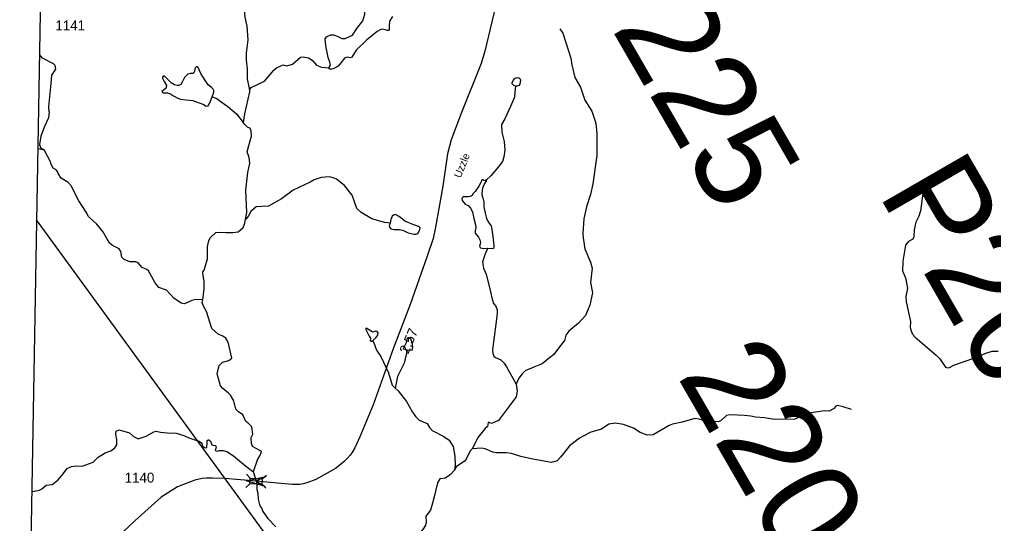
# Model space of a CAD drawing. Extents: x 2056842 to 2160602, y 826753 to 1016856.
# Drawn here: x 2058297 to 2070531, y 912171 to 918502 of the extents above; entities that cross this region are included whole.
import ezdxf

# ---------------------------------------------------------------- set-up
doc = ezdxf.new("R2010")
doc.units = 0
for name, color, linetype in [('Exist Boundary Political CountyLine', 7, 'Continuous'), ('Exist Hydrographic Creek Single Shore', 7, 'Continuous'), ('Exist Hydrographic Misc Water Feature', 7, 'Continuous'), ('Exist Road Secondary Mileage Hundredths English Label', 7, 'Continuous'), ('Exist Road Secondary Structure Pipe Number Label', 7, 'Continuous'), ('Exist Road Secondary Structure Standard Bridge Attributed CELL', 7, 'Continuous'), ('Exist Road Secondary Structure Standard Bridge CELL', 7, 'Continuous'), ('Exist Road Secondary Structure Standard Bridge Number Label', 7, 'Continuous'), ('Exist Road Secondary Type 41 Attributed', 7, 'Continuous'), ('Exist Road Secondary Type 51 Label', 7, 'Continuous'), ('Exist Road Secondary Type 51 Number Label', 7, 'Continuous'), ('Exist Utilities Electrical Transmission Line', 7, 'Continuous')]:
    doc.layers.add(name, color=color, linetype=linetype)

msp = doc.modelspace()

# ---------------------------------------------------------------- linework, layer by layer
at = {"layer": 'Exist Boundary Political CountyLine'}
msp.add_lwpolyline([(2059857, 1016190), (2059992, 1014583), (2060288, 1010619), (2060242, 1008371), (2060207, 1006771), (2060178, 1005306), (2060151, 1003994), (2060127, 1003052), (2060086, 1001470), (2060083, 1001043), (2059970, 996247), (2059900, 992965), (2059781, 986401), (2059707, 983126), (2059583, 976558), (2059387, 966720), (2059310, 963431), (2059198, 956451), (2059161, 955539), (2058927, 940380), (2058725, 928102), (2058408, 910016), (2058297, 904796)], dxfattribs=at)
at = {"layer": 'Exist Hydrographic Creek Single Shore'}
for points in [[(2060896, 919776), (2060908, 919728), (2060960, 919628), (2061040, 919384), (2061087, 919029), (2061128, 918532), (2061154, 918420), (2061166, 918247), (2061145, 918081), (2061145, 917989), (2061157, 917881), (2061157, 917757), (2061186, 917613)], [(2062182, 917893), (2062204, 917929), (2062196, 917967), (2062173, 918024), (2062145, 918170), (2062137, 918259), (2062153, 918282), (2062206, 918308), (2062247, 918311), (2062288, 918293), (2062347, 918262), (2062386, 918264), (2062480, 918303), (2062534, 918390), (2062611, 918485), (2062636, 918567), (2062636, 918592), (2062644, 918618)], [(2062984, 918541), (2062946, 918479), (2062941, 918418), (2062941, 918367), (2062933, 918362), (2062918, 918362), (2062859, 918382), (2062836, 918377), (2062790, 918349), (2062654, 918244), (2062524, 918116), (2062470, 918029), (2062450, 918021), (2062416, 918029), (2062380, 918016), (2062339, 917962), (2062299, 917914), (2062247, 917886), (2062204, 917873), (2062191, 917883), (2062182, 917893)], [(2065082, 918386), (2065120, 918330), (2065220, 918018), (2065233, 917934), (2065273, 917773), (2065343, 917653), (2065399, 917489), (2065484, 917349), (2065534, 917201), (2065550, 917065), (2065549, 916793), (2065500, 916437), (2065470, 916305), (2065418, 916149), (2065386, 915997), (2065371, 915813), (2065376, 915761), (2065397, 915621), (2065467, 915453), (2065489, 915377), (2065470, 915197), (2065494, 915069), (2065461, 914913), (2065405, 914785), (2065319, 914689), (2065195, 914588), (2065161, 914536), (2065141, 914468), (2065080, 914390), (2065010, 914292), (2064954, 914250), (2064863, 914177), (2064758, 914136), (2064650, 914087), (2064611, 914053), (2064570, 913997), (2064535, 913923)], [(2058668, 917344), (2058664, 917404), (2058695, 917696), (2058705, 917804), (2058753, 917876), (2058745, 917924), (2058725, 917944), (2058585, 918018), (2058547, 918062)], [(2061185, 917613), (2061209, 917649), (2061373, 917729), (2061493, 917867), (2061525, 917895), (2061609, 917931), (2061657, 917919), (2061725, 917940), (2061825, 918028), (2061860, 918032), (2061928, 918022), (2061973, 917990), (2062027, 917930), (2062092, 917903), (2062182, 917893)], [(2061186, 917613), (2061185, 917593), (2061123, 917318), (2061106, 917209)], [(2058668, 917344), (2058662, 917268), (2058610, 917156), (2058566, 917036), (2058547, 916930), (2058563, 916892), (2058595, 916868)], [(2061138, 915993), (2061152, 916077), (2061140, 916357), (2061167, 916580), (2061191, 916697), (2061183, 916768), (2061155, 916841), (2061178, 916920), (2061210, 917037), (2061208, 917109), (2061192, 917136), (2061160, 917149), (2061126, 917182), (2061106, 917208)], [(2060599, 914981), (2060513, 914985), (2060460, 914973), (2060368, 914929), (2060328, 914939), (2060236, 915003), (2060142, 915103), (2060046, 915135), (2060002, 915194), (2059918, 915346), (2059898, 915362), (2059837, 915386), (2059786, 915446), (2059758, 915458), (2059685, 915458), (2059610, 915488), (2059581, 915516), (2059569, 915588), (2059549, 915620), (2059465, 915663), (2059429, 915691), (2059345, 915841), (2059269, 915933), (2059184, 916005), (2059164, 916029), (2059136, 916081), (2059042, 916224), (2058946, 916412), (2058910, 916456), (2058820, 916508), (2058783, 916568), (2058775, 916592), (2058759, 916612), (2058719, 916636), (2058695, 916680), (2058683, 916724), (2058611, 916856), (2058595, 916868)], [(2060599, 914981), (2060609, 915049), (2060618, 915117), (2060618, 915214), (2060598, 915313), (2060602, 915334), (2060618, 915354), (2060657, 915494), (2060657, 915646), (2060677, 915726), (2060697, 915762), (2060765, 915826), (2060821, 915830), (2060890, 915826), (2060977, 915828), (2061043, 915836), (2061105, 915888), (2061126, 915945), (2061138, 915993)], [(2061236, 912813), (2061242, 912836), (2061288, 912972), (2061318, 913021), (2061337, 913072), (2061316, 913089), (2061222, 913139), (2061210, 913175), (2061209, 913251), (2061229, 913295), (2061215, 913387), (2061167, 913437), (2061139, 913451), (2061103, 913535), (2061047, 913574), (2061014, 913608), (2060991, 913714), (2060946, 913782), (2060922, 913810), (2060850, 913866), (2060820, 913902), (2060780, 914051), (2060804, 914157), (2060848, 914198), (2060927, 914218), (2060965, 914248), (2060919, 914450), (2060887, 914498), (2060853, 914526), (2060791, 914550), (2060711, 914622), (2060645, 914833), (2060610, 914902), (2060592, 914949), (2060599, 914981)], [(2070343, 914268), (2070433, 914312), (2070513, 914336), (2070589, 914337)], [(2064535, 913923), (2064547, 913832), (2064535, 913763), (2064438, 913634), (2064312, 913465), (2064225, 913428), (2064197, 913441), (2064183, 913439), (2064175, 913388), (2064141, 913361), (2064059, 913256), (2063984, 913108)], [(2059493, 913122), (2059519, 913158), (2059522, 913228), (2059506, 913295), (2059510, 913332), (2059549, 913348), (2059677, 913308), (2059729, 913262), (2059789, 913234), (2059887, 913268), (2059986, 913324), (2060012, 913330), (2060067, 913320), (2060150, 913309), (2060264, 913304), (2060363, 913276), (2060425, 913249), (2060489, 913226), (2060554, 913205), (2060581, 913188), (2060589, 913175), (2060590, 913150), (2060620, 913127), (2060639, 913122), (2060649, 913132), (2060655, 913184), (2060656, 913214), (2060665, 913222), (2060677, 913220), (2060695, 913207), (2060713, 913161), (2060728, 913154), (2060756, 913150), (2060768, 913139), (2060765, 913115), (2060755, 913093), (2060768, 913082), (2060783, 913081), (2060807, 913088), (2060855, 913088), (2060901, 913075), (2060985, 913021), (2061138, 912895), (2061224, 912829), (2061237, 912813)], [(2058453, 912573), (2058482, 912576), (2058547, 912591), (2058580, 912605), (2058633, 912651), (2058706, 912662), (2058781, 912716), (2058829, 912772), (2058896, 912861), (2058949, 912889), (2059004, 912897), (2059084, 912893), (2059222, 912940), (2059287, 913005), (2059373, 913060), (2059446, 913084), (2059493, 913122)], [(2063984, 913108), (2063958, 913084), (2063908, 912980), (2063884, 912948), (2063788, 912888), (2063760, 912842)], [(2061237, 912813), (2061270, 912701), (2061279, 912659), (2061277, 912599), (2061289, 912553), (2061297, 912475), (2061315, 912395), (2061341, 912359), (2061354, 912323), (2061418, 912235), (2061518, 912131)], [(2063760, 912842), (2063712, 912785), (2063646, 912742), (2063578, 912732), (2063547, 912682), (2063505, 912505), (2063486, 912427), (2063461, 912340), (2063401, 912264), (2063404, 912187), (2063398, 912152), (2063373, 912108), (2063304, 912025), (2063196, 911937), (2063074, 911780), (2063058, 911741), (2063042, 911649), (2063041, 911592), (2063067, 911536), (2063191, 911369), (2063228, 911293), (2063299, 911113), (2063310, 911045), (2063302, 910980)]]:
    msp.add_lwpolyline(points, dxfattribs=at)
at = {"layer": 'Exist Hydrographic Misc Water Feature'}
msp.add_line((2058528, 916883), (2058595, 916868), dxfattribs=at)
for points in [[(2060719, 917532), (2060737, 917590), (2060739, 917608), (2060731, 917625), (2060711, 917643), (2060667, 917683), (2060615, 917757), (2060577, 917822), (2060541, 917898), (2060529, 917908), (2060517, 917907), (2060508, 917900), (2060499, 917881), (2060497, 917848), (2060487, 917831), (2060474, 917825), (2060441, 917825), (2060412, 917816), (2060369, 917774), (2060343, 917722), (2060322, 917687), (2060298, 917671), (2060276, 917671), (2060245, 917681), (2060201, 917708), (2060137, 917772), (2060120, 917790), (2060102, 917790), (2060093, 917779), (2060093, 917765), (2060116, 917721), (2060143, 917672), (2060140, 917648), (2060128, 917633), (2060085, 917598), (2060093, 917583), (2060103, 917582), (2060158, 917580), (2060192, 917570), (2060230, 917544), (2060284, 917512), (2060318, 917502), (2060392, 917491), (2060476, 917483), (2060541, 917461), (2060611, 917434), (2060638, 917415), (2060665, 917416), (2060676, 917432), (2060698, 917477), (2060719, 917532)], [(2064529, 917663), (2064506, 917674), (2064487, 917695), (2064486, 917708), (2064496, 917736), (2064524, 917766), (2064546, 917773), (2064569, 917768), (2064583, 917760), (2064588, 917742), (2064583, 917691), (2064569, 917672), (2064550, 917664), (2064529, 917663)], [(2064529, 917663), (2064520, 917591), (2064513, 917528), (2064463, 917409), (2064393, 917254), (2064352, 917183), (2064357, 917088), (2064385, 916970), (2064393, 916862), (2064381, 916775), (2064363, 916720), (2064311, 916646), (2064217, 916540), (2064164, 916486)], [(2060719, 917532), (2060774, 917509), (2060829, 917467), (2060914, 917408), (2061024, 917315), (2061106, 917209)], [(2062951, 915942), (2062881, 915954), (2062721, 915997), (2062589, 916078), (2062536, 916129), (2062475, 916294), (2062380, 916418), (2062280, 916495), (2062236, 916515), (2062187, 916527), (2062087, 916518), (2062000, 916488), (2061949, 916460), (2061736, 916360), (2061588, 916248), (2061424, 916157), (2061342, 916155), (2061270, 916147), (2061204, 916089), (2061170, 916029), (2061139, 915993)], [(2064164, 916486), (2064152, 916481), (2064141, 916476), (2064128, 916479), (2064118, 916489), (2064110, 916488), (2064102, 916480), (2064097, 916461), (2064066, 916407), (2064019, 916343), (2063992, 916314), (2063983, 916293), (2063959, 916279), (2063937, 916275), (2063900, 916276), (2063873, 916274), (2063860, 916265), (2063854, 916250), (2063858, 916228), (2063895, 916183), (2063933, 916164), (2063961, 916133), (2063987, 916088), (2064005, 916001), (2064024, 915924), (2064028, 915885), (2064022, 915848), (2064022, 915819), (2064038, 915797), (2064064, 915766), (2064079, 915733), (2064086, 915701), (2064083, 915682), (2064074, 915654), (2064078, 915641), (2064088, 915632), (2064128, 915627), (2064174, 915628)], [(2064174, 915628), (2064235, 915626), (2064248, 915629), (2064257, 915639), (2064258, 915665), (2064248, 915776), (2064234, 915863), (2064224, 915908), (2064184, 915964), (2064165, 916004), (2064151, 916068), (2064135, 916148), (2064132, 916212), (2064126, 916247), (2064112, 916279), (2064107, 916317), (2064116, 916387), (2064134, 916430), (2064161, 916470), (2064164, 916486)], [(2069705, 916507), (2069687, 916487), (2069681, 916387), (2069637, 916287), (2069613, 916098), (2069594, 916031), (2069556, 915957), (2069536, 915859), (2069528, 915774), (2069518, 915742), (2069462, 915714), (2069426, 915666), (2069391, 915466), (2069389, 915346), (2069425, 915258), (2069449, 915126), (2069430, 915022), (2069432, 914954), (2069486, 914710), (2069482, 914634), (2069497, 914590), (2069514, 914550), (2069548, 914511), (2069811, 914285), (2069857, 914241), (2069929, 914133), (2069953, 914125), (2069977, 914129), (2070033, 914159), (2070343, 914268)], [(2062951, 915942), (2062941, 915910), (2062944, 915893), (2062961, 915873), (2063002, 915864), (2063070, 915864), (2063120, 915852), (2063180, 915824), (2063249, 915806), (2063280, 915807), (2063303, 915818), (2063326, 915866), (2063330, 915883), (2063322, 915894), (2063309, 915902), (2063249, 915923), (2063189, 915946), (2063137, 915970), (2063087, 916010), (2063059, 916033), (2063019, 916051), (2062993, 916045), (2062978, 916031), (2062963, 915988), (2062951, 915942)], [(2064174, 915628), (2064167, 915601), (2064151, 915572), (2064135, 915520), (2064111, 915455), (2064124, 915379), (2064160, 915303), (2064214, 915083), (2064234, 914991), (2064252, 914935), (2064278, 914899), (2064295, 914856), (2064298, 914821), (2064287, 914739), (2064281, 914675), (2064238, 914355), (2064241, 914307), (2064254, 914275), (2064274, 914255), (2064344, 914227), (2064386, 914187), (2064416, 914139), (2064535, 913923)], [(2062737, 914470), (2062773, 914504), (2062799, 914538), (2062804, 914563), (2062790, 914582), (2062772, 914589), (2062759, 914582), (2062741, 914574), (2062727, 914580), (2062660, 914621), (2062653, 914625), (2062649, 914620), (2062648, 914609), (2062662, 914574), (2062691, 914523), (2062704, 914497), (2062701, 914467), (2062710, 914460), (2062715, 914459), (2062737, 914470)], [(2062737, 914470), (2062745, 914454), (2062782, 914350), (2062834, 914270), (2062930, 914062), (2062980, 913910), (2063017, 913870)], [(2063159, 914446), (2063165, 914489), (2063179, 914509), (2063191, 914509), (2063209, 914493), (2063225, 914449)], [(2063166, 914348), (2063130, 914187), (2063044, 914018), (2063017, 913870)], [(2063166, 914348), (2063118, 914359), (2063159, 914446)], [(2063225, 914449), (2063233, 914385), (2063225, 914345), (2063166, 914348)], [(2063017, 913870), (2063052, 913838), (2063157, 913705), (2063235, 913569), (2063275, 913509), (2063315, 913469), (2063419, 913429), (2063447, 913377), (2063479, 913341), (2063625, 913265), (2063692, 913218), (2063744, 913138), (2063764, 913018), (2063770, 912902), (2063760, 912842)], [(2068746, 913601), (2068643, 913637), (2068572, 913653), (2068550, 913645), (2068523, 913613), (2068465, 913581), (2068409, 913585), (2068239, 913560), (2068195, 913548), (2068035, 913480), (2067779, 913477), (2067653, 913497), (2067542, 913508), (2067483, 913519), (2067403, 913527), (2067223, 913538), (2067179, 913526), (2067111, 913466), (2067075, 913450), (2066967, 913458), (2066887, 913466), (2066835, 913483), (2066779, 913491), (2066619, 913443), (2066497, 913419), (2066459, 913403), (2066257, 913284), (2066181, 913280), (2066091, 913316), (2066009, 913369), (2065885, 913416), (2065778, 913433), (2065698, 913418), (2065606, 913355), (2065473, 913318), (2065375, 913269), (2065329, 913241), (2065206, 913148), (2065131, 913049), (2065091, 913005), (2065049, 912957), (2064980, 912937), (2064722, 912984), (2064596, 913011), (2064476, 913051), (2064412, 913059), (2064288, 913059), (2064244, 913067), (2064144, 913110), (2064100, 913118), (2063984, 913108)]]:
    msp.add_lwpolyline(points, dxfattribs=at)
at = {"layer": 'Exist Road Secondary Structure Standard Bridge Attributed CELL'}
msp.add_lwpolyline([(2061381, 912634), (2061149, 912707), (2061387, 912760), (2061270, 912701)], close=True, dxfattribs=at)
at = {"layer": 'Exist Road Secondary Structure Standard Bridge CELL'}
for p, q in [((2061149, 912792), (2061196, 912741)), ((2061347, 912734), (2061398, 912780)), ((2061142, 912624), (2061192, 912670)), ((2061344, 912665), (2061390, 912614))]:
    msp.add_line(p, q, dxfattribs=at)
msp.add_lwpolyline([(2061196, 912741), (2061347, 912734), (2061343, 912664), (2061192, 912670)], close=True, dxfattribs=at)
at = {"layer": 'Exist Road Secondary Type 41 Attributed'}
for points in [[(2064320, 918862), (2064141, 918105), (2064094, 917950), (2063848, 917335), (2063720, 916991), (2063673, 916816), (2063615, 916410), (2063523, 915895), (2063492, 915750), (2063418, 915531), (2063206, 914922), (2062989, 914366), (2062739, 913661), (2062572, 913259), (2062508, 913123), (2062478, 913072), (2062450, 913031), (2062414, 912988), (2062381, 912954), (2062345, 912924), (2062265, 912861), (2062021, 912723), (2061908, 912683), (2061859, 912668), (2061819, 912659), (2061727, 912660), (2061539, 912676), (2061270, 912701)], [(2061270, 912701), (2060876, 912735), (2060723, 912742), (2060640, 912741), (2060593, 912738), (2060500, 912716), (2060282, 912631), (2060076, 912502), (2059746, 912205), (2059527, 912001), (2059336, 911843), (2059266, 911749), (2059158, 911469), (2059026, 911087), (2058929, 910823), (2058765, 910513), (2058582, 910277), (2058409, 910069)]]:
    msp.add_lwpolyline(points, dxfattribs=at)
at = {"layer": 'Exist Utilities Electrical Transmission Line'}
msp.add_lwpolyline([(2070229, 900032), (2067063, 904400), (2063349, 909347), (2058513, 915984)], dxfattribs=at)

# ---------------------------------------------------------------- texts
at = {"layer": 'Exist Road Secondary Mileage Hundredths English Label'}
msp.add_text('2.57', height=125, rotation=66.5642, dxfattribs=at).set_placement((2063178, 914290))
at = {"layer": 'Exist Road Secondary Structure Pipe Number Label'}
msp.add_text('P208', height=1230.3, rotation=300, dxfattribs=at).set_placement((2069072, 916321))
at = {"layer": 'Exist Road Secondary Structure Standard Bridge Number Label'}
for s, p in [('225', (2065726, 918389)), ('220', (2066548, 914026))]:
    msp.add_text(s, height=1230.3, rotation=300, dxfattribs=at).set_placement(p)
at = {"layer": 'Exist Road Secondary Type 51 Label'}
msp.add_text('Uzzle', height=95, rotation=68.1006, dxfattribs=at).set_placement((2063838, 916503))
at = {"layer": 'Exist Road Secondary Type 51 Number Label'}
for s, p in [('1141', (2058748, 918365)), ('1140', (2059619, 912685))]:
    msp.add_text(s, height=125, dxfattribs=at).set_placement(p)

doc.saveas('drawing.dxf')
